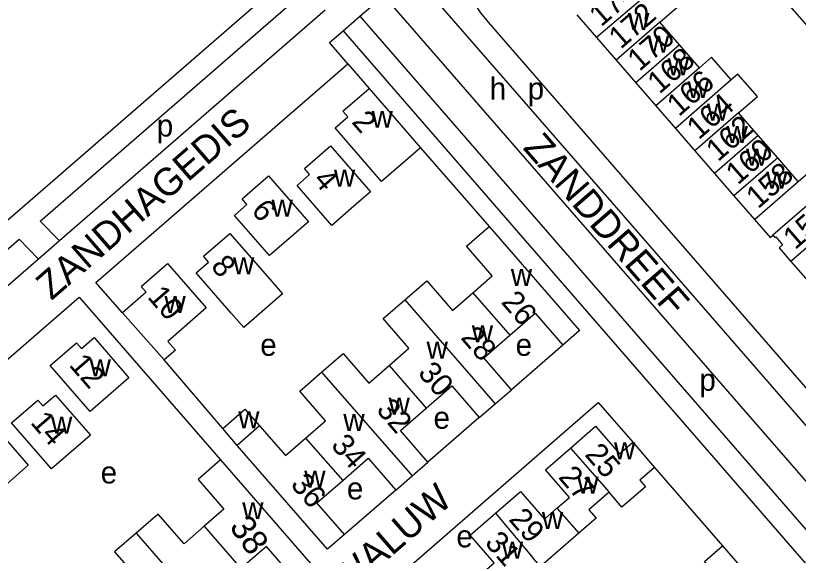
# Model space of a CAD drawing. Extents: x 155854 to 157362, y 383621 to 384685.
# Drawn here: x 156185.4 to 156327, y 384245.6 to 384343.2 of the extents above; entities that cross this region are included whole.
import ezdxf

# ---------------------------------------------------------------- set-up
doc = ezdxf.new("R2010")
doc.units = 0
for name, color, linetype in [('BLT_Basislijn', 7, 'Continuous'), ('BLT_Bebouwing', 7, 'Continuous'), ('BLT_Centroide', 7, 'Continuous'), ('BLT_Huisnummer', 7, 'Continuous'), ('BLT_Huisnummer_ tussenligend', 7, 'Continuous'), ('BLT_Onderverdeling_panden', 7, 'Continuous'), ('BLT_Straatnaam', 7, 'Continuous')]:
    doc.layers.add(name, color=color, linetype=linetype)

msp = doc.modelspace()

# ---------------------------------------------------------------- linework, layer by layer
at = {"layer": 'BLT_Basislijn'}
for p, q in [((156317.2, 384354.46), (156338.19, 384330.3)), ((156295.38, 384307.06), (156257, 384351.17)), ((156132.85, 384261.87), (156233.02, 384348.89)), ((156288.49, 384304.89), (156251.99, 384346.91)), ((156189.84, 384306.07), (156235.65, 384345.87)), ((156241.39, 384344.23), (156193.31, 384302.46)), ((156247.66, 384343.12), (156375.44, 384195.93)), ((156244.65, 384340.49), (156372.35, 384193.39)), ((156245.49, 384334.54), (156242.2, 384338.35)), ((156258.61, 384319.3), (156271.07, 384305.07)), ((156189.84, 384306.07), (156193.31, 384302.46)), ((156344.96, 384249.98), (156295.38, 384307.06)), ((156336.18, 384249.98), (156288.49, 384304.89)), ((156135.5, 384258.87), (156186.06, 384302.79)), ((156186.06, 384302.79), (156189.53, 384299.17)), ((156193.31, 384302.46), (156189.53, 384299.17)), ((156189.53, 384299.17), (156138.87, 384255.17)), ((156204.75, 384289.44), (156199.89, 384294.93)), ((156196.87, 384292.31), (156222.48, 384262.83)), ((156284.37, 384283.62), (156275.09, 384275.55)), ((156222.85, 384268.5), (156212.26, 384280.94)), ((156249.73, 384237.56), (156290.8, 384273.23)), ((156290.8, 384273.23), (156297.05, 384266.03)), ((156269.27, 384270.5), (156259.99, 384262.44)), ((156300.98, 384261.49), (156313.28, 384247.3)), ((156254.18, 384257.39), (156244.9, 384249.32))]:
    msp.add_line(p, q, dxfattribs=at)
for points in [[(156257, 384351.17), (156257.88, 384351.94), (156258.91, 384352.56), (156260.15, 384352.93), (156261.52, 384352.97), (156262.51, 384352.77), (156263.55, 384352.35), (156264.38, 384351.69), (156265.2, 384350.74), (156265.95, 384349.66), (156266.78, 384348.25), (156267.56, 384346.76), (156268.35, 384345.48), (156269.51, 384343.74), (156270.87, 384342.04)], [(156247.66, 384343.12), (156251.99, 384346.91)], [(156244.65, 384340.49), (156247.66, 384343.12)], [(156270.87, 384342.04), (156329.13, 384275), (156387.17, 384208.19)], [(156242.2, 384338.35), (156244.65, 384340.49)], [(156199.89, 384294.93), (156245.49, 384334.54)], [(156245.49, 384334.54), (156249.36, 384330.07)], [(156326.98, 384313.22), (156340.32, 384324.8)], [(156319.05, 384306.37), (156321.92, 384303.11), (156322.37, 384303.51)], [(156155.19, 384248.2), (156151.27, 384252.7), (156196.87, 384292.31)]]:
    msp.add_lwpolyline(points, dxfattribs=at)
at = {"layer": 'BLT_Bebouwing'}
for p, q in [((156305.49, 384337.94), (156301.93, 384342.04)), ((156309.11, 384333.78), (156305.49, 384337.94)), ((156249.36, 384330.07), (156258.61, 384319.3)), ((156319.73, 384321.57), (156316.17, 384325.66)), ((156323.25, 384317.51), (156319.73, 384321.57)), ((156326.98, 384313.22), (156323.25, 384317.51)), ((156332.5, 384312.33), (156322.37, 384303.51)), ((156209.01, 384293.21), (156204.75, 384289.44)), ((156212.26, 384280.94), (156204.75, 384289.44)), ((156212.92, 384284.28), (156214.3, 384282.72)), ((156214.3, 384282.72), (156212.26, 384280.94)), ((156272.16, 384273.01), (156275.09, 384275.55)), ((156269.27, 384270.5), (156272.16, 384273.01)), ((156269.19, 384270.36), (156269.17, 384270.34)), ((156297.05, 384266.03), (156300.98, 384261.49)), ((156222.48, 384262.83), (156238.81, 384244.04)), ((156257.1, 384259.93), (156259.99, 384262.44)), ((156254.18, 384257.39), (156257.1, 384259.93)), ((156313.28, 384247.3), (156317.21, 384242.78))]:
    msp.add_line(p, q, dxfattribs=at)
for points in [[(156301.93, 384342.04), (156305.35, 384345.03), (156301.81, 384349.1), (156298.42, 384346.08)], [(156286.92, 384343.36), (156290.47, 384339.26)], [(156290.47, 384339.26), (156294.02, 384335.18)], [(156314.83, 384331.63), (156311.29, 384335.7), (156309.11, 384333.78)], [(156294.02, 384335.18), (156297.59, 384331.07)], [(156316.17, 384325.66), (156319.57, 384328.59), (156316.02, 384332.67), (156314.83, 384331.63)], [(156245.5, 384324.91), (156244.59, 384325.94), (156249.36, 384330.07)], [(156297.59, 384331.07), (156301.2, 384326.91)], [(156301.2, 384326.91), (156304.74, 384322.84)], [(156258.61, 384319.3), (156251.56, 384313.24), (156249.29, 384315.88), (156243.22, 384322.94), (156245.5, 384324.91)], [(156304.74, 384322.84), (156308.26, 384318.79)], [(156242.38, 384319.67), (156249.61, 384311.38), (156246.59, 384308.74), (156242.6, 384305.29), (156236.32, 384312.52), (156238.54, 384314.51)], [(156238.54, 384314.51), (156237.64, 384315.55), (156242.38, 384319.67)], [(156308.26, 384318.79), (156311.82, 384314.69)], [(156311.82, 384314.69), (156315.34, 384310.64)], [(156231.12, 384314.22), (156238.36, 384305.91), (156231.35, 384299.81), (156225.01, 384307.09), (156227.25, 384309.04)], [(156227.25, 384309.04), (156226.38, 384310.09), (156231.12, 384314.22)], [(156319.05, 384306.37), (156326.98, 384313.22)], [(156315.34, 384310.64), (156319.05, 384306.37)], [(156268.11, 384293.08), (156271.63, 384296.15), (156266.97, 384301.51), (156271.07, 384305.07)], [(156271.07, 384305.07), (156287.4, 384286.25), (156284.37, 384283.62)], [(156224.15, 384303.83), (156231.39, 384295.53), (156233.68, 384292.9), (156226.66, 384286.79), (156224.37, 384289.42), (156218.04, 384296.69), (156220.31, 384298.65)], [(156220.31, 384298.65), (156219.41, 384299.69), (156224.15, 384303.83)], [(156322.37, 384303.51), (156322.75, 384303.08), (156322.9, 384303.22), (156324.15, 384301.78), (156323.51, 384301.21), (156325.63, 384298.77)], [(156325.63, 384298.77), (156329.17, 384294.7)], [(156209.01, 384293.21), (156208.13, 384294.24), (156212.89, 384298.37)], [(156212.89, 384298.37), (156219.87, 384290.35)], [(156255.81, 384291.82), (156259.77, 384295.26), (156264.43, 384289.89), (156268.11, 384293.08)], [(156252.94, 384279.91), (156256.55, 384283.04), (156251.89, 384288.41), (156255.81, 384291.82)], [(156219.87, 384290.35), (156212.92, 384284.28)], [(156274.79, 384285.39), (156279.37, 384289.37), (156284.37, 384283.62)], [(156197.31, 384283.01), (156199.58, 384284.98), (156205.9, 384277.7), (156198.87, 384271.57)], [(156275.09, 384275.55), (156270.09, 384281.31), (156274.79, 384285.39)], [(156198.87, 384271.57), (156191.66, 384279.9), (156196.41, 384284.04), (156197.31, 384283.01)], [(156240.75, 384278.73), (156244.65, 384282.12), (156249.31, 384276.75), (156252.94, 384279.91)], [(156237.85, 384266.79), (156241.45, 384269.92), (156236.78, 384275.28), (156240.75, 384278.73)], [(156259.64, 384272.23), (156264.28, 384276.26), (156269.27, 384270.5)], [(156190.34, 384272.61), (156192.59, 384274.57), (156198.92, 384267.29), (156191.88, 384261.2), (156184.67, 384269.52), (156189.43, 384273.65), (156190.34, 384272.61)], [(156222.85, 384268.5), (156226.87, 384272.02), (156229.51, 384269)], [(156259.99, 384262.44), (156254.99, 384268.19), (156259.64, 384272.23)], [(156179.09, 384267.16), (156181.34, 384269.14), (156187.66, 384261.86), (156180.64, 384255.76), (156173.43, 384264.05), (156178.18, 384268.19), (156179.09, 384267.16)], [(156225.49, 384265.47), (156222.85, 384268.5)], [(156229.51, 384269), (156234.21, 384263.63), (156237.85, 384266.79)], [(156285.79, 384264.99), (156290.31, 384268.92), (156294.63, 384263.94), (156297.05, 384266.03)], [(156244.9, 384249.32), (156241.84, 384246.66), (156225.49, 384265.47)], [(156283.32, 384254.11), (156285.57, 384256.06), (156281.24, 384261.04), (156285.79, 384264.99)], [(156222.48, 384262.83), (156218.41, 384259.3), (156223.07, 384253.93), (156219.5, 384250.83)], [(156244.57, 384259.13), (156249.18, 384263.14), (156254.18, 384257.39)], [(156300.98, 384261.49), (156298.31, 384259.17), (156299.36, 384257.96), (156295.08, 384254.27), (156292.74, 384256.99)], [(156244.9, 384249.32), (156239.9, 384255.08), (156244.57, 384259.13)], [(156272.2, 384253.18), (156276.72, 384257.11), (156281.05, 384252.13), (156283.32, 384254.11)], [(156292.74, 384256.99), (156289.1, 384253.82), (156290.41, 384252.31), (156287.26, 384249.58)], [(156219.5, 384250.83), (156215.86, 384247.67), (156211.2, 384253.03), (156207.21, 384249.57)], [(156269.73, 384242.3), (156271.97, 384244.24), (156267.64, 384249.23), (156272.2, 384253.18)], [(156207.21, 384249.57), (156203.31, 384246.18), (156207.97, 384240.81), (156204.37, 384237.68)], [(156287.26, 384249.58), (156280.34, 384243.57), (156279.03, 384245.08)], [(156235.77, 384241.39), (156230.76, 384247.16), (156226.16, 384243.17)], [(156307.69, 384239.79), (156311.31, 384242.94), (156310, 384244.45), (156313.28, 384247.3)]]:
    msp.add_lwpolyline(points, dxfattribs=at)
at = {"layer": 'BLT_Onderverdeling_panden'}
for p, q in [((156298.42, 384346.08), (156290.47, 384339.26)), ((156301.93, 384342.04), (156294.02, 384335.18)), ((156305.49, 384337.94), (156297.59, 384331.07)), ((156309.11, 384333.78), (156301.2, 384326.91)), ((156314.83, 384331.63), (156304.74, 384322.84)), ((156316.17, 384325.66), (156308.26, 384318.79)), ((156319.73, 384321.57), (156311.82, 384314.69)), ((156323.25, 384317.51), (156315.34, 384310.64)), ((156336.26, 384308), (156325.63, 384298.77)), ((156268.11, 384293.08), (156274.79, 384285.39)), ((156255.81, 384291.82), (156272.16, 384273.01)), ((156252.94, 384279.91), (156259.64, 384272.23)), ((156240.75, 384278.73), (156257.1, 384259.93)), ((156229.51, 384269), (156225.49, 384265.47)), ((156237.85, 384266.79), (156244.57, 384259.13)), ((156285.79, 384264.99), (156292.74, 384256.99)), ((156283.32, 384254.11), (156287.26, 384249.58)), ((156272.2, 384253.18), (156279.03, 384245.08)), ((156219.5, 384250.83), (156226.16, 384243.17)), ((156207.21, 384249.57), (156223.59, 384230.81))]:
    msp.add_line(p, q, dxfattribs=at)

# ---------------------------------------------------------------- texts
at = {"layer": 'BLT_Centroide'}
for s, p in [('w', (156296.18, 384340.62)), ('w', (156299.76, 384336.56)), ('w', (156303.34, 384332.44)), ('h', (156271.15, 384328.06)), ('w', (156306.93, 384328.31)), ('p', (156278.02, 384328.06)), ('w', (156310.45, 384324.25)), ('w', (156249.78, 384322.94)), ('p', (156210.93, 384321.36)), ('w', (156313.99, 384320.19)), ('w', (156317.53, 384316.09)), ('w', (156242.97, 384312.31)), ('w', (156321.17, 384311.94)), ('w', (156231.69, 384306.84)), ('w', (156224.72, 384296.45)), ('w', (156274.97, 384294.34)), ('w', (156212.31, 384289.44)), ('w', (156267.91, 384284.12)), ('e', (156229.65, 384281.68)), ('e', (156275.84, 384281.68)), ('w', (156259.73, 384281.16)), ('w', (156198.78, 384277.98)), ('p', (156309.08, 384275.35)), ('w', (156252.85, 384271.03)), ('w', (156191.8, 384267.59)), ('w', (156225.65, 384268.58)), ('w', (156244.67, 384268.06)), ('e', (156260.99, 384268.48)), ('w', (156293.64, 384262.97)), ('e', (156200.78, 384258.57)), ('w', (156237.6, 384257.84)), ('w', (156287, 384256.73)), ('e', (156245.32, 384255.69)), ('w', (156226.38, 384252.12)), ('w', (156280.59, 384250.34)), ('e', (156265.12, 384247.02)), ('w', (156273.34, 384244.98))]:
    msp.add_text(s, height=4, dxfattribs=at).set_placement(p)
at = {"layer": 'BLT_Huisnummer'}
for s, height, rotation, p in [('174', 4, 40.9877, (156291.31, 384341.09)), ('170', 4, 40.9877, (156298.24, 384333.03)), ('166', 4, 40.9877, (156305.37, 384324.85)), ('2', 4, 310.9787, (156246.04, 384323.93)), ('162', 4, 40.9877, (156312.45, 384316.68)), ('158', 4, 40.9877, (156319.7, 384308.16)), ('4', 4, 310.9787, (156239.06, 384313.41)), ('6', 4, 310.9787, (156227.87, 384307.87)), ('156', 4, 40.9826, (156326.4, 384300.76)), ('8', 4, 310.9787, (156220.56, 384297.78)), ('10', 4, 310.9787, (156209.09, 384292.26)), ('26', 4, 310.9824, (156273.08, 384291.32)), ('12', 4, 310.9787, (156194.92, 384279.95)), ('30', 4, 310.9824, (156258.01, 384278.47)), ('14', 4, 310.9787, (156187.93, 384269.54)), ('25', 4, 310.9336, (156288.2, 384263.74)), ('36', 4, 310.9824, (156234.97, 384258.3)), ('29', 4, 310.9336, (156274.46, 384252)), ('38', 4.5, 305.2061, (156223.93, 384250.73))]:
    msp.add_text(s, height=height, rotation=rotation, dxfattribs=at).set_placement(p)
at = {"layer": 'BLT_Huisnummer_ tussenligend'}
for s, rotation, p in [('172', 40.9877, (156294.85, 384337.04)), ('168', 40.9877, (156301.85, 384328.92)), ('164', 40.9877, (156308.97, 384320.66)), ('160', 40.9877, (156316.03, 384312.48)), ('28', 310.9824, (156265.77, 384284.89)), ('32', 310.9824, (156250.49, 384271.81)), ('34', 310.9824, (156242.28, 384265.39)), ('27', 310.9336, (156283.43, 384259.65)), ('31', 310.9336, (156270.11, 384247.77))]:
    msp.add_text(s, height=4, rotation=rotation, dxfattribs=at).set_placement(p)
at = {"layer": 'BLT_Straatnaam'}
for s, rotation, p in [('ZANDHAGEDIS', 40.9815, (156191.87, 384291.59)), ('ZANDDREEF', 310.9827, (156277.03, 384319.24)), ('ZANDZWALUW', 40.9825, (156228.49, 384223.69))]:
    msp.add_text(s, height=5, rotation=rotation, dxfattribs=at).set_placement(p)

doc.saveas('drawing.dxf')
